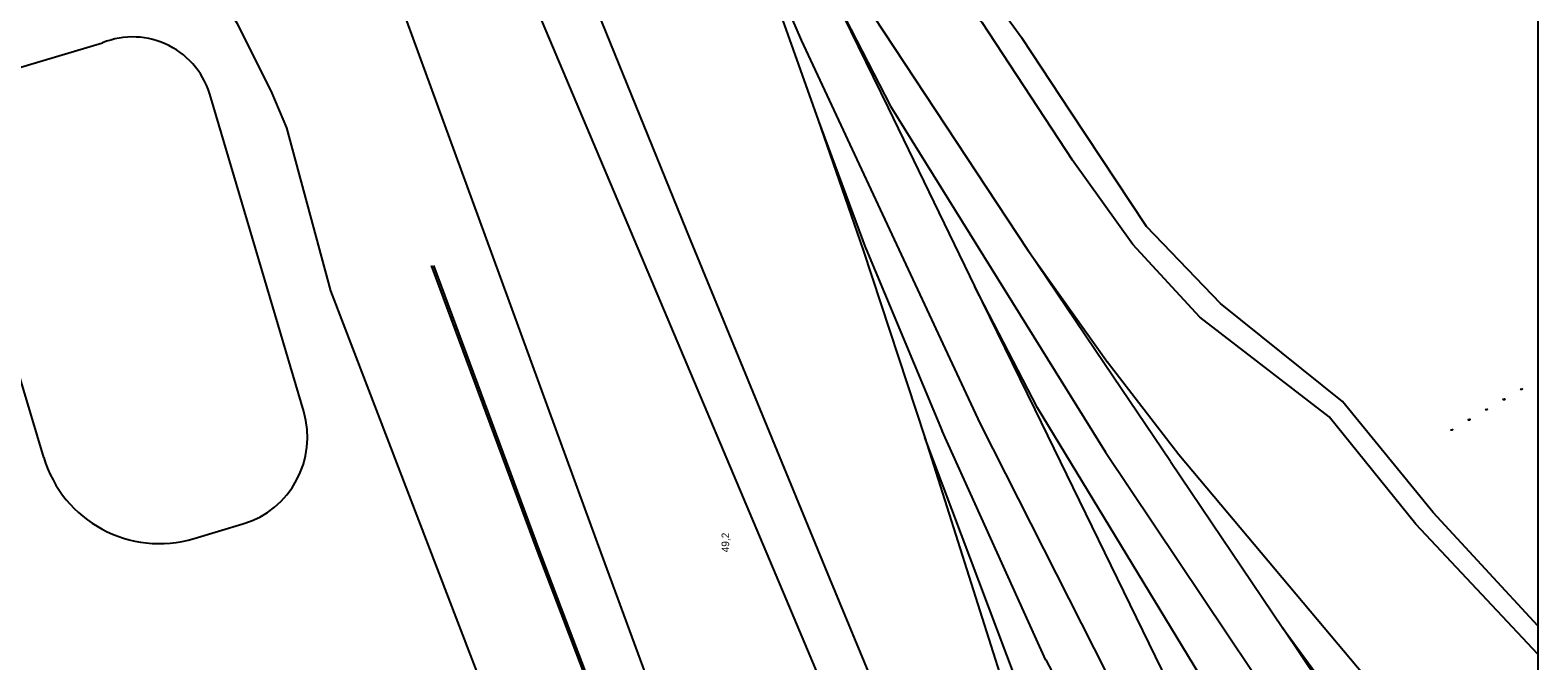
# Model space of a CAD drawing. Extents: x -932963 to -932666, y -737039 to -736000.
# Drawn here: x -932796.60368 to -932796.58871, y -736668.95505 to -736668.94879 of the extents above; entities that cross this region are included whole.
import ezdxf

# ---------------------------------------------------------------- set-up
doc = ezdxf.new("R2010")
doc.units = 0
for name, color, linetype in [('Border', 7, 'Continuous'), ('Implicitní', 7, 'Continuous'), ('Koleje_stávající', 7, 'Continuous'), ('Komunikace_stávající', 7, 'Continuous'), ('Oplocení_stávající_betonové', 7, 'Continuous'), ('SL_05_KOMUNIKACE', 7, 'Continuous')]:
    doc.layers.add(name, color=color, linetype=linetype)

# ---------------------------------------------------------------- blocks, each defined once
blk = doc.blocks.new('GPLO225')
at = {"layer": 'Implicitní'}
blk.add_arc((0, 0), 0.00025, 0, 180, dxfattribs=at)
blk = doc.blocks.new('přehledka')
at = {"layer": 'Border'}
blk.add_lwpolyline([(0, 0), (0.09991516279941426, 0), (0.09991516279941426, -0.06521838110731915), (0, -0.06521838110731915)], close=True, dxfattribs=at)
at = {"layer": 'Koleje_stávající'}
for points in [[(0.07021389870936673, -0.04768805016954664), (0.0731158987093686, -0.04662405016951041), (0.0759258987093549, -0.045598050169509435), (0.0790858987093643, -0.044442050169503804), (0.0826538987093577, -0.043138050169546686), (0.08506789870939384, -0.04226005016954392), (0.0883658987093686, -0.04105005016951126), (0.0913138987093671, -0.03997405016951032), (0.09556989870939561, -0.03842205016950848), (0.0984598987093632, -0.03735805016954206), (0.09991516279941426, -0.036821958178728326)], [(0.03445734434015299, -0.06521838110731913), (0.036093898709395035, -0.06463005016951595), (0.04202189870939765, -0.06243405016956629), (0.0462318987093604, -0.06083805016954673), (0.053853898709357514, -0.05786005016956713), (0.057567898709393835, -0.05638005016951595), (0.06646389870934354, -0.05271205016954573), (0.07220389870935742, -0.050292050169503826), (0.07886789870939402, -0.04748005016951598), (0.0843098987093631, -0.045184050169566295), (0.08998389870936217, -0.042780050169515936), (0.0970738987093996, -0.03980405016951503), (0.09991516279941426, -0.03862719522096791)], [(0.03707951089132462, -0.06521838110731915), (0.0423098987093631, -0.06328005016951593), (0.0465698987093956, -0.06166605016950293), (0.05413589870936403, -0.05872005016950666), (0.06680589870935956, -0.053566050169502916), (0.07260589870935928, -0.05116405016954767), (0.0793358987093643, -0.04839405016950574), (0.08490189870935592, -0.04613605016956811), (0.09028589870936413, -0.044012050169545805), (0.0972998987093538, -0.041326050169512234), (0.09991516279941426, -0.0403290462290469)], [(0.08797569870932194, -0.04868965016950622), (0.08543629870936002, -0.04967485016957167), (0.0833004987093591, -0.05059485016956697), (0.07568049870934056, -0.05414905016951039), (0.06922669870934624, -0.05741405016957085)], [(0.0879726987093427, -0.04869085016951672), (0.08541029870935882, -0.04961705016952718), (0.08171189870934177, -0.05092925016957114)], [(0.08908329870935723, -0.04884865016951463), (0.08797369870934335, -0.049455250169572), (0.08594689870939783, -0.05060845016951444), (0.07913269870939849, -0.055093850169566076)], [(0.08440069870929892, -0.05113105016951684), (0.08195849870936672, -0.05232105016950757), (0.07841649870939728, -0.05403305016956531), (0.07596669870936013, -0.055228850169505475), (0.07054209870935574, -0.057871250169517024), (0.06574909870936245, -0.06052825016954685), (0.05903593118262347, -0.06521838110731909)], [(0.08440069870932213, -0.05113105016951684), (0.08199049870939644, -0.052367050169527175), (0.0751196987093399, -0.056634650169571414), (0.06719969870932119, -0.06193325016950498)], [(0.08171189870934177, -0.05092925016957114), (0.07913269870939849, -0.05182165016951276)], [(0.08171189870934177, -0.05092925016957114), (0.07915769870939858, -0.05187645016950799)], [(0.07913069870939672, -0.051822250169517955), (0.07541009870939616, -0.05304845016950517), (0.07058929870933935, -0.054578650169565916)], [(0.0791632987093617, -0.051874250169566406), (0.07553729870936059, -0.05339225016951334)], [(0.0532065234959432, -0.06521838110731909), (0.06063189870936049, -0.06015325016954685), (0.06605249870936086, -0.05692725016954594), (0.07063089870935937, -0.05484865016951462), (0.07541009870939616, -0.05304845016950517)], [(0.05320652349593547, -0.0652183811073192), (0.06063189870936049, -0.06015325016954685), (0.06605249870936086, -0.05692725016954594), (0.07063089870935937, -0.05484865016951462), (0.07541009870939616, -0.05304845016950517)], [(0.05320652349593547, -0.0652183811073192), (0.06063189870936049, -0.06015325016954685), (0.06605249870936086, -0.05692725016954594), (0.07063089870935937, -0.05484865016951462), (0.07541009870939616, -0.05304845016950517)], [(0.07098709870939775, -0.05545265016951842), (0.07554109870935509, -0.05339065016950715)], [(0.07599769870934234, -0.05528145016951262), (0.07841649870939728, -0.054033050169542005)], [(0.07600629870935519, -0.055276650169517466), (0.07016849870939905, -0.05881525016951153), (0.06478249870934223, -0.06234985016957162)], [(0.07493189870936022, -0.05792305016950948), (0.07687209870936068, -0.05661705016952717), (0.07913269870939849, -0.055093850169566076)], [(0.07913269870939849, -0.055093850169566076), (0.07690689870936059, -0.05667105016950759)], [(0.07099469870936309, -0.05544885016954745), (0.0652186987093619, -0.058488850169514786), (0.05557305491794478, -0.06521838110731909)], [(0.07001209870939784, -0.06233385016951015), (0.0750636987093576, -0.05808785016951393), (0.07691129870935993, -0.05666765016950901)], [(0.07493189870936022, -0.05792305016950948), (0.07161789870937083, -0.06015305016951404)], [(0.06420773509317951, -0.06521838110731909), (0.0674128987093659, -0.06297625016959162), (0.07161789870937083, -0.06015305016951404)], [(0.07161789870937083, -0.06015305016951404), (0.0675508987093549, -0.06314165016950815)]]:
    blk.add_lwpolyline(points, dxfattribs=at)
at = {"layer": 'Komunikace_stávající'}
for points in [[(0.08627789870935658, -0.037758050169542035), (0.08363389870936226, -0.039394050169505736), (0.08224789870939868, -0.040084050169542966), (0.08155850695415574, -0.04037674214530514), (0.07831989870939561, -0.0412500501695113), (0.07529989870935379, -0.042404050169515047), (0.07174989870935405, -0.04376805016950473), (0.06721389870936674, -0.04551005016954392), (0.06387989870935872, -0.04677005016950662), (0.06302782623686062, -0.04706505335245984), (0.06120989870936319, -0.04773405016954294), (0.05674789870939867, -0.04935205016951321), (0.05208789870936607, -0.051014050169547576), (0.04977189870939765, -0.05189805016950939), (0.04848589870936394, -0.052330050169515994), (0.04734589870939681, -0.05270005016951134), (0.04302789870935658, -0.05413205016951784), (0.03886189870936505, -0.05539005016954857), (0.03673589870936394, -0.05607005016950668), (0.03664486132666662, -0.05610461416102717)], [(0.08515589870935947, -0.05271005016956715), (0.08461989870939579, -0.05310605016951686), (0.08365989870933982, -0.05417605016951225), (0.08092789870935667, -0.0559760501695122)], [(0.08544189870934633, -0.053284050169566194), (0.08480989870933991, -0.05374205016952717), (0.08388389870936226, -0.05458205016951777), (0.08334789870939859, -0.05497405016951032)], [(0.07960389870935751, -0.05745005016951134), (0.08187389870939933, -0.05594605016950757), (0.08334789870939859, -0.05497405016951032)], [(0.0777978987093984, -0.05851005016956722), (0.0792458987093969, -0.05717405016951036), (0.08092789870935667, -0.0559760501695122)], [(0.07612389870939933, -0.06134005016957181), (0.07806989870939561, -0.05892005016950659), (0.07960389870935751, -0.05745005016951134)], [(0.07368589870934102, -0.0627960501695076), (0.07581989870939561, -0.06107805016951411), (0.0777978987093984, -0.05851005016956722)], [(0.07166705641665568, -0.06521838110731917), (0.07391989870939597, -0.06314205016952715), (0.07612389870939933, -0.06134005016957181)], [(0.07110577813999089, -0.06521838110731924), (0.07368589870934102, -0.0627960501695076)]]:
    blk.add_lwpolyline(points, dxfattribs=at)
at = {"layer": 'Oplocení_stávající_betonové'}
for points in [[(0.07882806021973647, -0.043247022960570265), (0.07314789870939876, -0.04535205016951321), (0.06976789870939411, -0.04664005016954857), (0.06998951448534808, -0.047241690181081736)], [(0.07882806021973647, -0.043289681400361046), (0.07316197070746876, -0.04538949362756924), (0.06981910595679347, -0.04666334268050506), (0.07002704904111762, -0.04722786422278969)]]:
    blk.add_lwpolyline(points, dxfattribs=at)
at = {"layer": 'SL_05_KOMUNIKACE'}
for p, q in [((0.08046743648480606, -0.02740511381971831), (0.08325050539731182, -0.03672147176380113)), ((0.07501426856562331, -0.035553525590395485), (0.0784191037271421, -0.034535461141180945)), ((0.0734022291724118, -0.038539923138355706), (0.07369089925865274, -0.03950620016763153)), ((0.07592679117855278, -0.04071684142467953), (0.08216567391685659, -0.03886887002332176))]:
    blk.add_line(p, q, dxfattribs=at)
for centre, radius, start, end in [((0.07570180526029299, -0.037852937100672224), 0.0024000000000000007, 106.64695426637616, 196.63323198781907), ((0.08176645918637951, -0.03731947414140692), 0.0016, 284.44847135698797, 21.947170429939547), ((0.0754155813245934, -0.0389909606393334), 0.0018000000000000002, 196.63323198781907, 286.4994135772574)]:
    blk.add_arc(centre, radius, start, end, dxfattribs=at)
at = {"layer": 'Oplocení_stávající_betonové', "xscale": 0.08000000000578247, "yscale": 0.08000000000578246, "rotation": 120.31952828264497}
for p in [(0.07557176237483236, -0.06350734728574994), (0.07577369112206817, -0.06385263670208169), (0.07597561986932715, -0.06419792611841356), (0.07617754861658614, -0.064543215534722), (0.07637947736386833, -0.06488850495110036)]:
    blk.add_blockref('GPLO225', p, dxfattribs=at)
at = {"layer": 'Koleje_stávající'}
blk.add_text('49,2', height=0.00015000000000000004, dxfattribs=at).set_placement((0.07312789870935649, -0.049162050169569))

msp = doc.modelspace()

# ---------------------------------------------------------------- block references
at = {"layer": 'SL_05_KOMUNIKACE', "xscale": 0.5, "yscale": 0.5, "rotation": 90}
msp.add_blockref('přehledka', (-932796.621318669, -736668.9905401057), dxfattribs=at)

doc.saveas('drawing.dxf')
